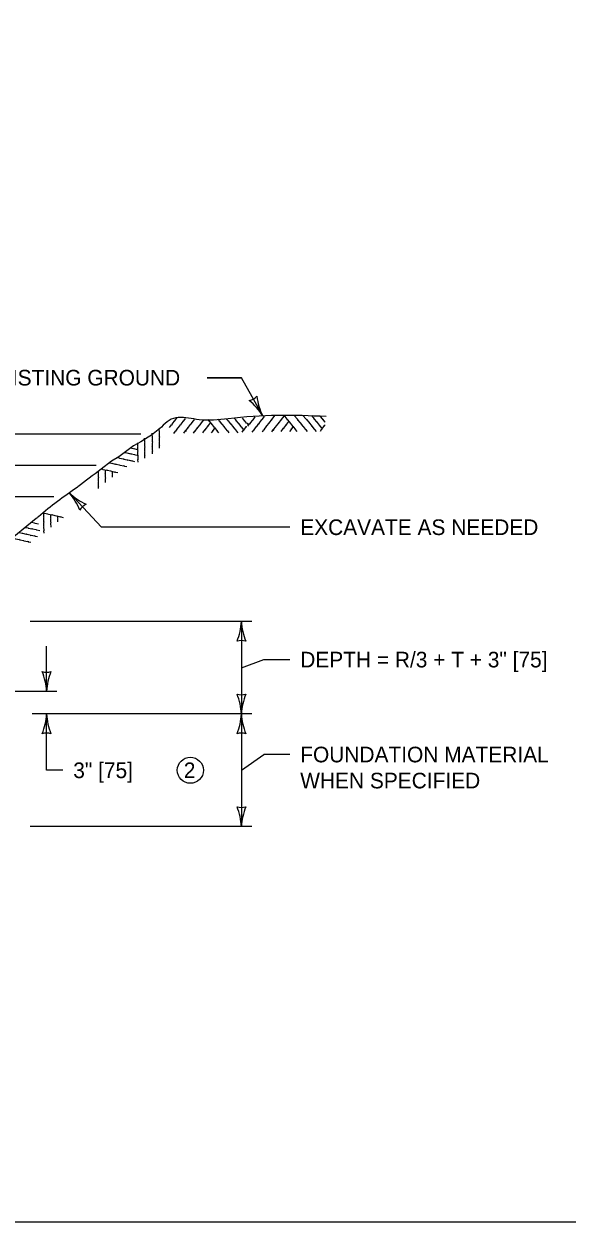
# Model space of a CAD drawing. Extents: x 49991.4 to 50021, y 49987.6 to 50011.4.
# Drawn here: x 50010.306 to 50012.392, y 49987.799 to 49992.398 of the extents above; entities that cross this region are included whole.
import ezdxf

# ---------------------------------------------------------------- set-up
doc = ezdxf.new("R2010")
doc.units = 0
for name, color, linetype in [('Level 1', 7, 'Continuous'), ('Level 2', 7, 'Continuous'), ('Level 3', 7, 'Continuous')]:
    doc.layers.add(name, color=color, linetype=linetype)

msp = doc.modelspace()

# ---------------------------------------------------------------- linework, layer by layer
at = {"layer": 'Level 1'}
for p, q in [((50008.7832, 49990.8245), (50010.7552, 49990.8245)), ((50008.7832, 49990.7045), (50010.5831, 49990.7045)), ((50009.404, 49990.5845), (50010.4213, 49990.5845)), ((50010.3536, 49990.4994), (50010.2312, 49990.3999))]:
    msp.add_line(p, q, dxfattribs=at)
msp.add_lwpolyline([(49999.3835, 49998.9992), (50016.7501, 49998.9992), (50016.7501, 49987.7988), (49999.3835, 49987.7988)], close=True, dxfattribs=at)
for points in [[(50010.8656, 49990.8489), (50010.8734, 49990.8591), (50010.8754, 49990.8596), (50010.8755, 49990.8616), (50010.8838, 49990.8721), (50010.8835, 49990.8741), (50010.8856, 49990.8742), (50010.8953, 49990.8872)], [(50010.882, 49990.8262), (50010.8881, 49990.8345), (50010.8898, 49990.8341), (50010.8894, 49990.8356), (50010.8977, 49990.8463), (50010.8972, 49990.8484), (50010.8992, 49990.8486), (50010.9076, 49990.8595), (50010.9095, 49990.86), (50010.9097, 49990.862), (50010.918, 49990.8725), (50010.9177, 49990.8745), (50010.9197, 49990.8746), (50010.9264, 49990.8835)], [(50011.0505, 49990.8814), (50011.0554, 49990.8757), (50011.0546, 49990.8741), (50011.0562, 49990.8742), (50011.0647, 49990.8637), (50011.0668, 49990.8637), (50011.0666, 49990.8617), (50011.0754, 49990.8511), (50011.0754, 49990.8491), (50011.0773, 49990.8484), (50011.0856, 49990.838), (50011.0877, 49990.8379), (50011.0873, 49990.8358), (50011.0933, 49990.8287)], [(50011.0847, 49990.8815), (50011.0894, 49990.876), (50011.0886, 49990.8744), (50011.0902, 49990.8744), (50011.0987, 49990.864), (50011.1009, 49990.864), (50011.1006, 49990.862), (50011.1094, 49990.8514), (50011.1094, 49990.8493), (50011.1113, 49990.8487), (50011.1197, 49990.8382), (50011.1217, 49990.8381), (50011.1214, 49990.8361), (50011.1274, 49990.829)], [(50011.1142, 49990.8842), (50011.1195, 49990.878), (50011.1187, 49990.8764), (50011.1203, 49990.8764), (50011.1288, 49990.8659), (50011.131, 49990.866), (50011.1307, 49990.8639), (50011.1395, 49990.8534), (50011.1395, 49990.8513), (50011.1414, 49990.8507), (50011.1483, 49990.842)], [(50011.1441, 49990.8853), (50011.1509, 49990.8773), (50011.1501, 49990.8757), (50011.1518, 49990.8757), (50011.1602, 49990.8652), (50011.1614, 49990.8653)], [(50011.1665, 49990.8538), (50011.1743, 49990.864), (50011.1762, 49990.8645), (50011.1764, 49990.8665), (50011.1847, 49990.877), (50011.1844, 49990.879), (50011.1865, 49990.8791), (50011.1942, 49990.8895)], [(50011.1828, 49990.8311), (50011.189, 49990.8394), (50011.1907, 49990.839), (50011.1903, 49990.8405), (50011.1986, 49990.8512), (50011.1981, 49990.8533), (50011.2001, 49990.8535), (50011.2084, 49990.8644), (50011.2104, 49990.8649), (50011.2106, 49990.8669), (50011.2189, 49990.8774), (50011.2186, 49990.8794), (50011.2206, 49990.8795), (50011.2298, 49990.8918)], [(50011.2217, 49990.8325), (50011.2279, 49990.8408), (50011.2296, 49990.8404), (50011.2292, 49990.842), (50011.2375, 49990.8526), (50011.237, 49990.8547), (50011.239, 49990.8549), (50011.2474, 49990.8659), (50011.2493, 49990.8664), (50011.2495, 49990.8683), (50011.2578, 49990.8789), (50011.2575, 49990.8809), (50011.2595, 49990.881), (50011.2699, 49990.8948)], [(50011.2585, 49990.8324), (50011.2638, 49990.8397), (50011.2655, 49990.8393), (50011.2651, 49990.8408), (50011.2734, 49990.8515), (50011.2729, 49990.8535), (50011.2749, 49990.8538), (50011.2833, 49990.8647), (50011.2852, 49990.8652), (50011.2854, 49990.8672), (50011.2937, 49990.8777), (50011.2934, 49990.8797), (50011.2954, 49990.8798), (50011.3049, 49990.8924)], [(50011.3036, 49990.8959), (50011.3163, 49990.8811), (50011.3156, 49990.8794), (50011.3172, 49990.8795), (50011.3257, 49990.869), (50011.3278, 49990.869), (50011.3276, 49990.867), (50011.3363, 49990.8564), (50011.3364, 49990.8544), (50011.3383, 49990.8537), (50011.3466, 49990.8433), (50011.3487, 49990.8432), (50011.3483, 49990.8411), (50011.3543, 49990.834)], [(50011.3439, 49990.8951), (50011.3562, 49990.8806), (50011.3555, 49990.879), (50011.3571, 49990.8791), (50011.3656, 49990.8686), (50011.3677, 49990.8686), (50011.3675, 49990.8666), (50011.3763, 49990.856), (50011.3763, 49990.854), (50011.3782, 49990.8533), (50011.3865, 49990.8429), (50011.3885, 49990.8427), (50011.3882, 49990.8407), (50011.3942, 49990.8336)], [(50011.3776, 49990.8957), (50011.3903, 49990.8809), (50011.3895, 49990.8793), (50011.3911, 49990.8793), (50011.3996, 49990.8689), (50011.4018, 49990.8689), (50011.4015, 49990.8669), (50011.4103, 49990.8563), (50011.4103, 49990.8542), (50011.4122, 49990.8536), (50011.4206, 49990.8431), (50011.4226, 49990.843), (50011.4222, 49990.841), (50011.4283, 49990.8339)], [(50011.4104, 49990.8945), (50011.4204, 49990.8829), (50011.4196, 49990.8813), (50011.4212, 49990.8813), (50011.4297, 49990.8708), (50011.4318, 49990.8709), (50011.4316, 49990.8688), (50011.4404, 49990.8583), (50011.4404, 49990.8562), (50011.4423, 49990.8556), (50011.4492, 49990.8469)], [(50011.4436, 49990.8918), (50011.4518, 49990.8822), (50011.451, 49990.8806), (50011.4526, 49990.8806), (50011.4611, 49990.8701), (50011.4622, 49990.8702)], [(50010.8272, 49990.7697), (50010.8268, 49990.7787), (50010.8284, 49990.7794), (50010.8271, 49990.7803), (50010.827, 49990.7939), (50010.8254, 49990.7951), (50010.8267, 49990.7966), (50010.8265, 49990.8104), (50010.8277, 49990.8119), (50010.8266, 49990.8136), (50010.8266, 49990.827), (50010.8251, 49990.8284), (50010.8266, 49990.8297), (50010.8262, 49990.8455)], [(50010.9209, 49990.8276), (50010.927, 49990.8359), (50010.9287, 49990.8355), (50010.9283, 49990.8371), (50010.9366, 49990.8477), (50010.9361, 49990.8498), (50010.9381, 49990.85), (50010.9465, 49990.861), (50010.9484, 49990.8615), (50010.9486, 49990.8634), (50010.9569, 49990.874), (50010.9566, 49990.876), (50010.9587, 49990.8761), (50010.9612, 49990.8795)], [(50010.9576, 49990.8275), (50010.9629, 49990.8348), (50010.9646, 49990.8344), (50010.9642, 49990.8359), (50010.9725, 49990.8466), (50010.972, 49990.8487), (50010.974, 49990.8489), (50010.9824, 49990.8598), (50010.9843, 49990.8603), (50010.9845, 49990.8623), (50010.9928, 49990.8728), (50010.9925, 49990.8748), (50010.9946, 49990.8749), (50010.9977, 49990.8791)], [(50010.9931, 49990.8291), (50011.0026, 49990.8415), (50011.0045, 49990.842), (50011.0048, 49990.8439), (50011.0131, 49990.8545), (50011.0127, 49990.8565), (50011.0148, 49990.8565), (50011.0222, 49990.8665)], [(50011.0125, 49990.8796), (50011.0154, 49990.8762), (50011.0147, 49990.8745), (50011.0163, 49990.8746), (50011.0248, 49990.8641), (50011.0269, 49990.8641), (50011.0267, 49990.8621), (50011.0355, 49990.8515), (50011.0355, 49990.8495), (50011.0374, 49990.8488), (50011.0457, 49990.8384), (50011.0478, 49990.8383), (50011.0474, 49990.8362), (50011.0534, 49990.8291)], [(50011.0264, 49990.8291), (50011.0323, 49990.8366), (50011.032, 49990.8386), (50011.034, 49990.8387), (50011.0397, 49990.8463)], [(50011.1437, 49990.8307), (50011.1497, 49990.8389), (50011.1515, 49990.8385), (50011.1511, 49990.84), (50011.1594, 49990.8507), (50011.1588, 49990.8528), (50011.1609, 49990.853), (50011.1614, 49990.8537)], [(50011.1637, 49990.8653), (50011.1648, 49990.8653), (50011.1646, 49990.8633), (50011.1678, 49990.8593)], [(50011.294, 49990.834), (50011.3035, 49990.8464), (50011.3054, 49990.8469), (50011.3056, 49990.8488), (50011.314, 49990.8594), (50011.3136, 49990.8613), (50011.3157, 49990.8614), (50011.3235, 49990.8719)], [(50011.3273, 49990.834), (50011.3332, 49990.8415), (50011.3328, 49990.8435), (50011.3349, 49990.8436), (50011.3406, 49990.8512)], [(50011.4446, 49990.8356), (50011.4506, 49990.8438), (50011.4524, 49990.8434), (50011.452, 49990.8449), (50011.4603, 49990.8556), (50011.4597, 49990.8577), (50011.4618, 49990.8579), (50011.4623, 49990.8586)], [(50010.7438, 49990.7447), (50010.7436, 49990.7575), (50010.7448, 49990.7591), (50010.7437, 49990.7608), (50010.7437, 49990.7742), (50010.7422, 49990.7756), (50010.7438, 49990.777), (50010.7433, 49990.7899)], [(50010.7708, 49990.7309), (50010.7705, 49990.7412), (50010.7721, 49990.742), (50010.7708, 49990.7429), (50010.7707, 49990.7564), (50010.769, 49990.7578), (50010.7704, 49990.7592), (50010.7702, 49990.7729), (50010.7714, 49990.7745), (50010.7703, 49990.7762), (50010.7703, 49990.7896), (50010.7688, 49990.791), (50010.7703, 49990.7923), (50010.7699, 49990.8076)], [(50010.8002, 49990.7485), (50010.7999, 49990.7588), (50010.8015, 49990.7596), (50010.8002, 49990.7606), (50010.8001, 49990.774), (50010.7984, 49990.7754), (50010.7999, 49990.7768), (50010.7996, 49990.7906), (50010.8008, 49990.7922), (50010.7998, 49990.7938), (50010.7997, 49990.8073), (50010.7982, 49990.8086), (50010.7997, 49990.81), (50010.7993, 49990.8272)], [(50010.7267, 49990.7788), (50010.6705, 49990.7368), (50010.6422, 49990.7192), (50010.6023, 49990.6885)], [(50010.6929, 49990.7535), (50010.7009, 49990.7519), (50010.7012, 49990.7502), (50010.7025, 49990.7512), (50010.7157, 49990.7482), (50010.7173, 49990.7497), (50010.7184, 49990.7478), (50010.7318, 49990.7451), (50010.7331, 49990.7434), (50010.735, 49990.7442), (50010.7458, 49990.7416)], [(50010.7158, 49990.7707), (50010.7261, 49990.7686), (50010.7265, 49990.7669), (50010.7278, 49990.7679), (50010.7409, 49990.7649), (50010.7418, 49990.7657)], [(50010.7446, 49990.7161), (50010.7442, 49990.7263), (50010.7458, 49990.7271), (50010.7446, 49990.728), (50010.7444, 49990.7416), (50010.7426, 49990.7428), (50010.7442, 49990.7443), (50010.7441, 49990.7452)], [(50010.6348, 49990.7136), (50010.6422, 49990.7121), (50010.6426, 49990.7104), (50010.6438, 49990.7115), (50010.657, 49990.7085), (50010.6586, 49990.7098), (50010.6597, 49990.7081), (50010.6732, 49990.7053), (50010.6744, 49990.7037), (50010.6763, 49990.7044), (50010.6893, 49990.7014), (50010.691, 49990.7026), (50010.692, 49990.7007), (50010.7011, 49990.6989)], [(50010.6653, 49990.7335), (50010.6724, 49990.7322), (50010.6727, 49990.7304), (50010.674, 49990.7314), (50010.6871, 49990.7285), (50010.6888, 49990.7299), (50010.6899, 49990.7281), (50010.7033, 49990.7253), (50010.7046, 49990.7237), (50010.7065, 49990.7244), (50010.7196, 49990.7214), (50010.7212, 49990.7225), (50010.7222, 49990.7208), (50010.7314, 49990.7189)], [(50010.5933, 49990.6149), (50010.5929, 49990.6239), (50010.5945, 49990.6246), (50010.5933, 49990.6256), (50010.5931, 49990.6391), (50010.5914, 49990.6404), (50010.5929, 49990.6418), (50010.5927, 49990.6556), (50010.5938, 49990.6572), (50010.5928, 49990.6589), (50010.5927, 49990.6722), (50010.5913, 49990.6736), (50010.5928, 49990.675), (50010.5927, 49990.6802)], [(50010.6039, 49990.6898), (50010.6083, 49990.6889), (50010.6088, 49990.6872), (50010.61, 49990.6883), (50010.6232, 49990.6853), (50010.6249, 49990.6866), (50010.6259, 49990.6849), (50010.6394, 49990.6821), (50010.6407, 49990.6805), (50010.6426, 49990.6812), (50010.6556, 49990.6782), (50010.6573, 49990.6794), (50010.6583, 49990.6775), (50010.6674, 49990.6757)], [(50010.6201, 49990.6382), (50010.6199, 49990.6538), (50010.621, 49990.6554), (50010.6201, 49990.6571), (50010.62, 49990.6705), (50010.6185, 49990.6718), (50010.6201, 49990.6731), (50010.6197, 49990.6856)], [(50010.6462, 49990.6589), (50010.6462, 49990.6684), (50010.6447, 49990.6698), (50010.6462, 49990.6711), (50010.6459, 49990.6806)], [(50010.3794, 49990.5211), (50010.3986, 49990.5174), (50010.3991, 49990.5156), (50010.4003, 49990.5167), (50010.4134, 49990.5138), (50010.4151, 49990.5151), (50010.4162, 49990.5134), (50010.4296, 49990.5105), (50010.4309, 49990.509), (50010.4328, 49990.5096), (50010.4458, 49990.5066), (50010.4475, 49990.5078), (50010.4485, 49990.506), (50010.4576, 49990.5041)], [(50010.3835, 49990.4433), (50010.3832, 49990.4523), (50010.3847, 49990.4531), (50010.3835, 49990.454), (50010.3833, 49990.4675), (50010.3817, 49990.4688), (50010.3831, 49990.4703), (50010.3829, 49990.484), (50010.3841, 49990.4856), (50010.383, 49990.4873), (50010.383, 49990.5007), (50010.3815, 49990.5021), (50010.383, 49990.5034), (50010.3826, 49990.5192)], [(50010.4104, 49990.4666), (50010.4101, 49990.4823), (50010.4113, 49990.4838), (50010.4103, 49990.4854), (50010.4102, 49990.499), (50010.4088, 49990.5002), (50010.4103, 49990.5016), (50010.4099, 49990.5147)], [(50010.3349, 49990.4852), (50010.3473, 49990.4828), (50010.3476, 49990.481), (50010.3489, 49990.482), (50010.3621, 49990.4791), (50010.3629, 49990.4798)], [(50010.4365, 49990.4873), (50010.4364, 49990.4969), (50010.4349, 49990.4982), (50010.4364, 49990.4996), (50010.4362, 49990.5091)], [(50010.2615, 49990.4246), (50010.2734, 49990.4221), (50010.2738, 49990.4204), (50010.275, 49990.4215), (50010.2882, 49990.4185), (50010.2898, 49990.4199), (50010.2909, 49990.4182), (50010.3044, 49990.4153), (50010.3056, 49990.4138), (50010.3076, 49990.4144), (50010.3205, 49990.4114), (50010.3222, 49990.4125), (50010.3232, 49990.4107), (50010.3323, 49990.4089)], [(50010.2875, 49990.4457), (50010.2999, 49990.4435), (50010.3003, 49990.4418), (50010.3015, 49990.4428), (50010.3146, 49990.4399), (50010.3164, 49990.4413), (50010.3174, 49990.4395), (50010.3308, 49990.4367), (50010.3321, 49990.435), (50010.334, 49990.4358), (50010.3471, 49990.4328), (50010.3487, 49990.4339), (50010.3497, 49990.4321), (50010.3589, 49990.4303)], [(50010.3122, 49990.4657), (50010.3222, 49990.4638), (50010.3226, 49990.4621), (50010.3238, 49990.4631), (50010.337, 49990.4601), (50010.3386, 49990.4615), (50010.3398, 49990.4597), (50010.3532, 49990.457), (50010.3545, 49990.4553), (50010.3563, 49990.456), (50010.3672, 49990.4535)]]:
    msp.add_lwpolyline(points, dxfattribs=at)
for points in [[(50011.4671, 49990.8913), (50011.281, 49990.8955), (50011.0907, 49990.8829), (50010.9786, 49990.8786), (50010.8982, 49990.8871), (50010.8643, 49990.8765), (50010.8343, 49990.8506), (50010.7267, 49990.7788)], [(50010.6023, 49990.6885), (50010.5127, 49990.6209), (50010.5104, 49990.6191)], [(50010.5104, 49990.6191), (50010.362, 49990.5067), (50010.3536, 49990.4994)]]:
    msp.add_spline(points, degree=3, dxfattribs=at)
at = {"layer": 'Level 2'}
msp.add_circle((50010.9453, 49989.5331), 0.05, dxfattribs=at)
at = {"layer": 'Level 3'}
for p, q in [((50011.0093, 49991.0403), (50011.142, 49991.0403)), ((50011.142, 49991.0403), (50011.0098, 49991.0403)), ((50011.2231, 49990.8941), (50011.142, 49991.0403)), ((50011.1815, 49990.1045), (50010.3298, 49990.1045)), ((50011.1415, 49990.1045), (50011.1415, 49989.7493)), ((50010.3932, 49989.8361), (50010.3932, 49990.0095)), ((50011.1415, 49989.9269), (50011.2272, 49989.958)), ((50011.2272, 49989.958), (50011.3272, 49989.958)), ((50010.4332, 49989.8361), (50009.5057, 49989.8361)), ((50011.1815, 49989.7493), (50010.3384, 49989.7493)), ((50010.3932, 49989.5331), (50010.3932, 49989.7493)), ((50011.1415, 49989.7493), (50011.1415, 49989.3168)), ((50011.1415, 49989.5331), (50011.2272, 49989.5936)), ((50011.3272, 49989.5936), (50011.2272, 49989.5936)), ((50010.4557, 49989.5331), (50010.3932, 49989.5331)), ((50011.1815, 49989.3168), (50010.3298, 49989.3168))]:
    msp.add_line(p, q, dxfattribs=at)
msp.add_lwpolyline([(50011.3272, 49990.4662), (50010.6046, 49990.4662), (50010.4807, 49990.5983)], dxfattribs=at)
for centre, radius, start, end in [((50011.1609, 49991.0062), 0.0548, 281.1568, 316.8792), ((50011.0252, 49990.7711), 0.233, 31.8453, 51.0952), ((50011.4218, 49990.9938), 0.2223, 186.474, 206.6575), ((50010.6365, 49990.7569), 0.2223, 225.5098, 245.6933), ((50010.3031, 49990.4475), 0.233, 21.0721, 40.322), ((50010.5684, 49990.5048), 0.0548, 115.2881, 151.0105), ((50010.9088, 49990.116), 0.233, 337.9228, 357.1727), ((50011.3636, 49990.1136), 0.2223, 182.3605, 202.544), ((50011.1415, 49989.9763), 0.0548, 72.1388, 107.8612), ((50010.1711, 49989.827), 0.2223, 2.3605, 22.544), ((50010.3932, 49989.9643), 0.0548, 252.1388, 287.8612), ((50010.6259, 49989.8246), 0.233, 157.9228, 177.1727), ((50010.9193, 49989.7402), 0.2223, 2.3605, 22.544), ((50011.1415, 49989.8776), 0.0548, 252.1388, 287.8612), ((50011.3742, 49989.7379), 0.233, 157.9228, 177.1727), ((50010.1605, 49989.7608), 0.233, 337.9228, 357.1727), ((50010.6154, 49989.7585), 0.2223, 182.3605, 202.544), ((50010.9088, 49989.7608), 0.233, 337.9228, 357.1727), ((50011.3636, 49989.7585), 0.2223, 182.3605, 202.544), ((50010.3932, 49989.6211), 0.0548, 72.1388, 107.8612), ((50011.1415, 49989.6211), 0.0548, 72.1388, 107.8612), ((50010.9193, 49989.3077), 0.2223, 2.3605, 22.544), ((50011.1415, 49989.4451), 0.0548, 252.1388, 287.8612), ((50011.3742, 49989.3053), 0.233, 157.9228, 177.1727)]:
    msp.add_arc(centre, radius, start, end, dxfattribs=at)

# ---------------------------------------------------------------- texts
at = {"layer": 'Level 2'}
for s, p in [('EXISTING GROUND', (50010.1529, 49991.0103)), ('DEPTH = R/3 + T + 3" [75]', (50011.3672, 49989.928)), ('FOUNDATION MATERIAL', (50011.3672, 49989.5636)), ('2', (50010.9201, 49989.5031)), ('WHEN SPECIFIED', (50011.3672, 49989.4636))]:
    msp.add_text(s, height=0.06, dxfattribs=at).set_placement(p)
for s, p in [('EXCAVATE AS NEEDED', (50011.3672, 49990.4362)), ('3" [75]', (50010.4957, 49989.5031))]:
    msp.add_text(s, height=0.06, rotation=360, dxfattribs=at).set_placement(p)

doc.saveas('drawing.dxf')
